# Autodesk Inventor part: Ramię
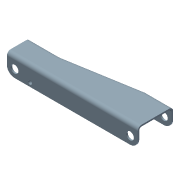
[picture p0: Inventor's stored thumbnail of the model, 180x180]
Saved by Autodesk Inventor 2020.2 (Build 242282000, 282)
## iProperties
Created: 2005-10
Part Number: Ramię
Document SubType Name: Modeling
Designer: F.Stasiak
Density: 1 g/cm^3
Material: Ogólny
Appearance: Niebieski pastelowy
Manager: www.cadconsulting.pl
Company: Fabian Stasiak CAD Consulting
Author: F.Stasiak
Subject: Zbiór ćwiczeń. Autodesk Inventor 2020. Kurs podstawowy
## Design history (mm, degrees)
sketch "Szkic1"
  geometry: L1 (-1300, -230)-(0, -230); L2 (0, -230)-(0, 230); L3 (0, 230)-(-350, 230); L4 (-350, 230)-(-1300, 70); L5 (-1300, 70)-(-1300, -230); 2 further points
  constraints: 10 end point, 2 perpendicular, 1 coincident, 1 horizontal, 1 midpoint, 1 parallel
  dimensions: "d0" = 1300 distance of L1.start L1.end; "d1" = 460 distance of L1.end L2.end; "d2" = 300 distance of L4.end L1.start; "d3" = 350 distance of L2.end L3.end
extrude "Wyciągnięcie proste1" new body sketch "Szkic1" distance "d4" = 250; taper "d5" = 0 deg
sketch "Szkic3"
  geometry: L1 (250, 0)-(250, 300) reference; L2 (0, 300)-(250, 300) reference; L3 (0, 300)-(0, 0) reference; L4 (0, 0)-(250, 0) reference
extrude "Wyciągnięcie proste2" join sketch "Szkic3" distance "d7" = 400; taper "d8" = 0 deg
fillet "Zaokrąglenie6" dims "d29" = 100
fillet "Zaokrąglenie7" dims "d30" = 50
feature "Skorupa1" dims "d12" = 20
fillet "Zaokrąglenie4" dims "d13" = 100
sketch "Szkic6"
  geometry: L1 (100, -100)-(300, -100); A1 r 100 centre (1600, -100) between (1600, -200) and (1700, -100) reference; A2 r 100 centre (100, -100) between (0, -100) and (100, -200) reference
  constraints: 2 end point, 1 horizontal
  dimensions: "d38" = 200 distance of L1.end L1.start
hole "Otwór3" sketch "Szkic6" at (100, -100), (1600, -100) diameter "d31" = 100; stored, may be unused: countersink angle "d35" = 90 deg, drill point angle "d37" = 118 deg; dims "d32" = 6, "d33" = 4, "d34" = 2, "d36" = 8
sketch "Szkic7"
  geometry: C1 r 50 at (100, -100) reference; 1 further point
  dimensions: "d47" = 50 vertical distance of point (300, -150) C1.centre; "d48" = 200 horizontal distance of point (300, -150) C1.centre
hole "Otwór4" sketch "Szkic7" at (300, -150) diameter "d40" = 50; stored, may be unused: countersink angle "d44" = 90 deg, drill point angle "d46" = 118 deg; dims "d41" = 6, "d42" = 4, "d43" = 2, "d45" = 8
sketch "Szkic8"
  geometry: C1 r 25 at (300, 150) reference; C2 r 45 at (300, 150)
  constraints: 1 centre point, 1 coincident
  dimensions: "d49" = 90 diameter of C2
extrude "Wyciągnięcie proste3" join sketch "Szkic8" distance "d50" = 30; taper "d51" = 0 deg
sketch "Szkic9"
  geometry: C1 r 25 at (300, -150) reference; C2 r 45 at (300, -150)
  constraints: 1 centre point, 1 coincident
  dimensions: "d52" = 90 diameter of C2
extrude "Wyciągnięcie proste4" join sketch "Szkic9" distance "d53" = 50; taper "d54" = 0 deg
node "Bryła1"
node "Korpusy bryłowe"
node "Korpusy powierzchniowe"
node "Pętla rzutowana2"
